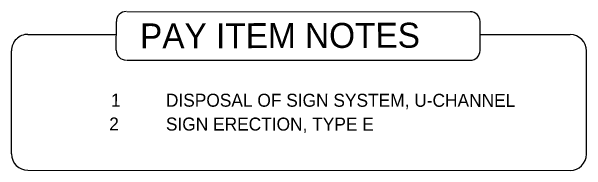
# Model space of a CAD drawing. Extents: x 50703 to 52785, y 49383 to 50479.
# Drawn here: x 52465.8 to 52785.3, y 49733 to 49821.2 of the extents above; entities that cross this region are included whole.
import ezdxf

# ---------------------------------------------------------------- set-up
doc = ezdxf.new("R2010")
doc.units = 0
for name, color, linetype in [('Default', 7, 'Continuous'), ('Prop Text Disposal Sign D E F CELL', 7, 'Continuous'), ('Prop Text Sign Erection_D E F CELL', 7, 'Continuous'), ('Sheet Title CELL', 7, 'Continuous')]:
    doc.layers.add(name, color=color, linetype=linetype)

msp = doc.modelspace()

# ---------------------------------------------------------------- linework, layer by layer
at = {"layer": 'Sheet Title CELL'}
for p, q in [((52524.04, 49799.73), (52524.05, 49815.76)), ((52726.2, 49799.64), (52726.21, 49815.66)), ((52474.9, 49808.55), (52524.04, 49808.53)), ((52726.2, 49808.43), (52776.26, 49808.41)), ((52465.78, 49742.25), (52465.81, 49799.47)), ((52785.32, 49742.11), (52785.35, 49799.32)), ((52474.87, 49733.16), (52776.23, 49733.02))]:
    msp.add_line(p, q, dxfattribs=at)
for points in [[(52529.96, 49821.21), (52721.22, 49821.12)], [(52529.95, 49794.28), (52721.2, 49794.19)]]:
    msp.add_lwpolyline(points, dxfattribs=at)
for centre, radius, start, end in [((52529.5, 49815.76), 5.45, 89.9734, 179.9734), ((52720.75, 49815.67), 5.45, 359.9734, 89.9734), ((52474.9, 49799.46), 9.09, 89.9734, 179.9734), ((52776.26, 49799.32), 9.09, 359.9734, 89.9734), ((52529.49, 49799.73), 5.45, 179.9734, 269.9734), ((52720.75, 49799.64), 5.45, 269.9734, 359.9734), ((52474.87, 49742.25), 9.09, 179.9734, 269.9734), ((52776.23, 49742.11), 9.09, 269.9734, 359.9734)]:
    msp.add_arc(centre, radius, start, end, dxfattribs=at)

# ---------------------------------------------------------------- texts
at = {"layer": 'Default'}
msp.add_text('PAY ITEM NOTES', height=13.8661, rotation=0.1557, dxfattribs=at).set_placement((52537.23, 49800.71))
at = {"layer": 'Prop Text Disposal Sign D E F CELL'}
for s, p in [('DISPOSAL OF SIGN SYSTEM, U-CHANNEL', (52551.59, 49768.41)), ('SIGN ERECTION, TYPE E', (52551.59, 49755.19))]:
    msp.add_text(s, height=7.1994, rotation=359.9734, dxfattribs=at).set_placement(p)
at = {"layer": 'Prop Text Sign Erection_D E F CELL'}
for s, p in [('1', (52521.05, 49768.42)), ('2', (52520.07, 49755.21))]:
    msp.add_text(s, height=7.2, rotation=359.9734, dxfattribs=at).set_placement(p)

doc.saveas('drawing.dxf')
